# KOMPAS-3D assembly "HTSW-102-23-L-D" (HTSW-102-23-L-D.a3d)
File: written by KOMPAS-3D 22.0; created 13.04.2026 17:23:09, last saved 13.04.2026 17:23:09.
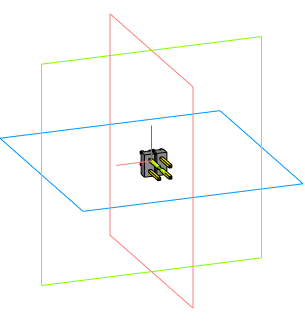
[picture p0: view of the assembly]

Document properties: Автор: Andrey; Полное имя файла: C:\Users\User1\Documents\HTSW-102-23-L-D.a3d

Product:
- Component [detail]: HTSW-102-23-L-D_body  | qty 1  | source file: HTSW-102-23-L-D_body.m3d
- Component [detail]: T-1S6-16-HTSW-1--23-2--L-D  | qty 1  | source file: T-1S6-16-HTSW-1--23-2--L-D.m3d
- Component [detail]: T-1S6-16-HTSW-1--23-2--L-D2  | qty 1  | source file: T-1S6-16-HTSW-1--23-2--L-D2.m3d
- Part/product: HTSW-102-23-L-D
    Комментарий: HTSW-102-23-L-D

Referenced files in C:\Users\User1\Documents\: HTSW-102-23-L-D_body.m3d, T-1S6-16-HTSW-1--23-2--L-D.m3d, T-1S6-16-HTSW-1--23-2--L-D2.m3d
